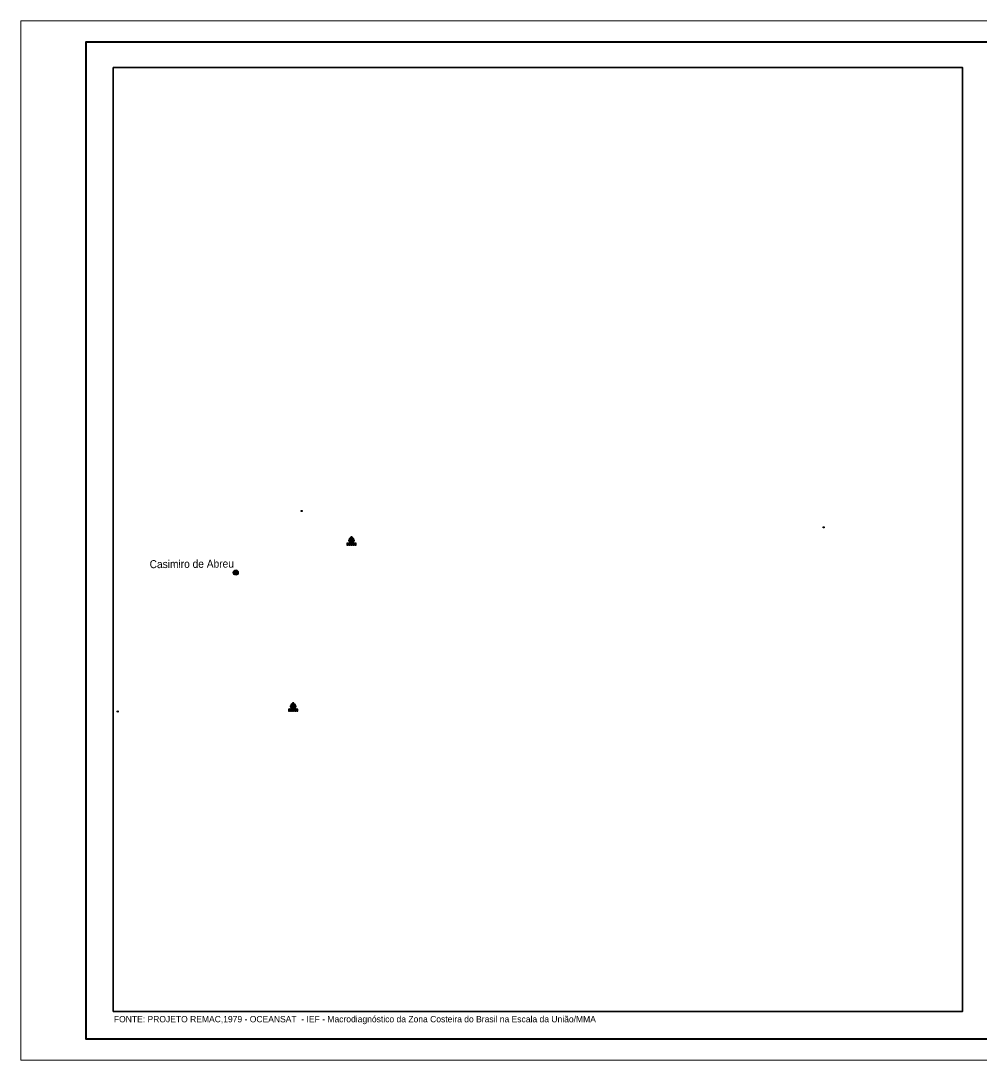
# Model space of a CAD drawing. Extents: x -6.3 to 58.7, y 19.8 to 60.6.
# Drawn here: x -6.29 to 31.28, y 19.82 to 60.58 of the extents above; entities that cross this region are included whole.
import ezdxf
from ezdxf.enums import TextEntityAlignment as Align

# ---------------------------------------------------------------- set-up
doc = ezdxf.new("R2010")
doc.units = 0
doc.header["$LTSCALE"] = 0.092
doc.header["$PDMODE"] = 32
doc.header["$PDSIZE"] = 0.046
for name, color, linetype, lineweight in [('2', 7, 'Continuous', 35), ('4', 7, 'Continuous', 25), ('58', 7, 'Continuous', 13), ('60', 7, 'Continuous', 40), ('63', 7, 'Continuous', 13)]:
    doc.layers.add(name, color=color, linetype=linetype, lineweight=lineweight)
for name, color, linetype in [('34', 7, 'Continuous'), ('37', 7, 'Continuous'), ('42', 7, 'Continuous'), ('44', 7, 'Continuous'), ('57', 7, 'Continuous')]:
    doc.layers.add(name, color=color, linetype=linetype)

msp = doc.modelspace()

# ---------------------------------------------------------------- hatches: boundary and pattern name
at = {"layer": '4'}
msp.add_hatch(color=256, dxfattribs=at).paths.add_polyline_path([(2.2372, 38.94214, 1), (2.03773, 38.94214, 1)])
at = {"layer": '58'}
for points in [[(6.85434, 40.05991), (6.85434, 40.09183), (6.84793, 40.08915), (6.84259, 40.0882), (6.82351, 40.09482), (6.80112, 40.1014), (6.78763, 40.09944), (6.76748, 40.0913), (6.76748, 40.15712), (6.78898, 40.19649), (6.7914, 40.20216), (6.79229, 40.20689), (6.79026, 40.21256), (6.78144, 40.21759), (6.76748, 40.22346), (6.76748, 40.27282), (6.73025, 40.27282), (6.73025, 40.30576), (6.6992, 40.30576), (6.6992, 40.33874), (6.64958, 40.33874), (6.64958, 40.30576), (6.61857, 40.30576), (6.61857, 40.27282), (6.58134, 40.27282), (6.58134, 40.22297), (6.56738, 40.21759), (6.55902, 40.21306), (6.55653, 40.20791), (6.55727, 40.20235), (6.5598, 40.19649), (6.58134, 40.15712), (6.58134, 40.0913), (6.56108, 40.09944), (6.5477, 40.1014), (6.52548, 40.09482), (6.50619, 40.0882), (6.50056, 40.08915), (6.49448, 40.09183), (6.49448, 40.05991), (6.50135, 40.05628), (6.50822, 40.05526), (6.52673, 40.06184), (6.54837, 40.06846), (6.56959, 40.06278), (6.58967, 40.05711), (6.60935, 40.06278), (6.62989, 40.06846), (6.65257, 40.06184), (6.67372, 40.05526), (6.69458, 40.06184), (6.71889, 40.06846), (6.74014, 40.06278), (6.75912, 40.05711), (6.77852, 40.06278), (6.80013, 40.06846), (6.82216, 40.06184), (6.84145, 40.05526), (6.84601, 40.05628)], [(6.85434, 40.01346), (6.85434, 40.04569), (6.84793, 40.043), (6.84281, 40.04206), (6.82408, 40.04868), (6.79927, 40.05526), (6.77862, 40.04939), (6.76001, 40.04361), (6.7411, 40.04939), (6.71764, 40.05526), (6.69497, 40.04868), (6.67461, 40.04206), (6.65374, 40.04868), (6.63118, 40.05526), (6.60886, 40.04939), (6.58878, 40.04361), (6.5692, 40.04939), (6.54709, 40.05526), (6.52605, 40.04868), (6.50687, 40.04206), (6.50096, 40.043), (6.49448, 40.04569), (6.49448, 40.01346), (6.50067, 40.01017), (6.50736, 40.00915), (6.52733, 40.01573), (6.54837, 40.02231), (6.56959, 40.01668), (6.58967, 40.011), (6.60935, 40.01668), (6.62989, 40.02231), (6.65257, 40.01573), (6.67372, 40.00915), (6.69543, 40.01573), (6.71889, 40.02231), (6.73936, 40.01668), (6.75912, 40.011), (6.77919, 40.01668), (6.80013, 40.02231), (6.82138, 40.01573), (6.84145, 40.00915), (6.84804, 40.01017)], [(6.74886, 40.23038), (6.67439, 40.25716), (6.59996, 40.23038), (6.59996, 40.25304), (6.63716, 40.25304), (6.63716, 40.28598), (6.71163, 40.28598), (6.71163, 40.25304), (6.74886, 40.25304)], [(4.56503, 33.55104), (4.56503, 33.58297), (4.55862, 33.58028), (4.55328, 33.57933), (4.5342, 33.58595), (4.51181, 33.59253), (4.49832, 33.59057), (4.47817, 33.58244), (4.47817, 33.64825), (4.49967, 33.68762), (4.50209, 33.6933), (4.50298, 33.69802), (4.50095, 33.7037), (4.49212, 33.70873), (4.47817, 33.71459), (4.47817, 33.76395), (4.44093, 33.76395), (4.44093, 33.79689), (4.40989, 33.79689), (4.40989, 33.82988), (4.36027, 33.82988), (4.36027, 33.79689), (4.32926, 33.79689), (4.32926, 33.76395), (4.29203, 33.76395), (4.29203, 33.7141), (4.27807, 33.70873), (4.26971, 33.70419), (4.26721, 33.69904), (4.26796, 33.69348), (4.27049, 33.68762), (4.29203, 33.64825), (4.29203, 33.58244), (4.27177, 33.59057), (4.25838, 33.59253), (4.23617, 33.58595), (4.21688, 33.57933), (4.21125, 33.58028), (4.20517, 33.58297), (4.20517, 33.55104), (4.21204, 33.54741), (4.21891, 33.54639), (4.23742, 33.55297), (4.25906, 33.55959), (4.28028, 33.55392), (4.30036, 33.54824), (4.32004, 33.55392), (4.34058, 33.55959), (4.36326, 33.55297), (4.3844, 33.54639), (4.40526, 33.55297), (4.42958, 33.55959), (4.45083, 33.55392), (4.4698, 33.54824), (4.4892, 33.55392), (4.51081, 33.55959), (4.53285, 33.55297), (4.55214, 33.54639), (4.5567, 33.54741)], [(4.56503, 33.5046), (4.56503, 33.53682), (4.55862, 33.53414), (4.5535, 33.53319), (4.53477, 33.53981), (4.50996, 33.54639), (4.48931, 33.54053), (4.47069, 33.53474), (4.45179, 33.54053), (4.42833, 33.54639), (4.40566, 33.53981), (4.38529, 33.53319), (4.36443, 33.53981), (4.34186, 33.54639), (4.31954, 33.54053), (4.29947, 33.53474), (4.27989, 33.54053), (4.25778, 33.54639), (4.23674, 33.53981), (4.21755, 33.53319), (4.21164, 33.53414), (4.20517, 33.53682), (4.20517, 33.5046), (4.21136, 33.5013), (4.21805, 33.50028), (4.23802, 33.50686), (4.25906, 33.51345), (4.28028, 33.50781), (4.30036, 33.50214), (4.32004, 33.50781), (4.34058, 33.51345), (4.36326, 33.50686), (4.3844, 33.50028), (4.40612, 33.50686), (4.42958, 33.51345), (4.45005, 33.50781), (4.4698, 33.50214), (4.48988, 33.50781), (4.51081, 33.51345), (4.53207, 33.50686), (4.55214, 33.50028), (4.55873, 33.5013)], [(4.45955, 33.72151), (4.38508, 33.74829), (4.31064, 33.72151), (4.31064, 33.74417), (4.34784, 33.74417), (4.34784, 33.77711), (4.42232, 33.77711), (4.42232, 33.74417), (4.45955, 33.74417)]]:
    msp.add_hatch(color=256, dxfattribs=at).paths.add_polyline_path(points)

# ---------------------------------------------------------------- linework, layer by layer
at = {"layer": '2'}
msp.add_lwpolyline([(-2.6635, 58.74412), (30.62637, 58.74412), (30.62637, 21.73), (-2.6635, 21.73)], close=True, dxfattribs=at)
at = {"layer": '34'}
msp.add_point((25.18317, 40.71409), dxfattribs=at)
at = {"layer": '37'}
msp.add_point((4.719, 41.35238), dxfattribs=at)
at = {"layer": '4'}
msp.add_circle((2.13747, 38.94214), 0.09974, dxfattribs=at)
at = {"layer": '42'}
msp.add_point((-2.48978, 33.49348), dxfattribs=at)
at = {"layer": '44'}
msp.add_point((25.18317, 40.71409), dxfattribs=at)
at = {"layer": '58', "lineweight": 25}
for points in [[(6.85434, 40.05991), (6.85434, 40.09183), (6.84793, 40.08915), (6.84259, 40.0882), (6.82351, 40.09482), (6.80112, 40.1014), (6.78763, 40.09944), (6.76748, 40.0913), (6.76748, 40.15712), (6.78898, 40.19649), (6.7914, 40.20216), (6.79229, 40.20689), (6.79026, 40.21256), (6.78144, 40.21759), (6.76748, 40.22346), (6.76748, 40.27282), (6.73025, 40.27282), (6.73025, 40.30576), (6.6992, 40.30576), (6.6992, 40.33874), (6.64958, 40.33874), (6.64958, 40.30576), (6.61857, 40.30576), (6.61857, 40.27282), (6.58134, 40.27282), (6.58134, 40.22297), (6.56738, 40.21759), (6.55902, 40.21306), (6.55653, 40.20791), (6.55727, 40.20235), (6.5598, 40.19649), (6.58134, 40.15712), (6.58134, 40.0913), (6.56108, 40.09944), (6.5477, 40.1014), (6.52548, 40.09482), (6.50619, 40.0882), (6.50056, 40.08915), (6.49448, 40.09183), (6.49448, 40.05991), (6.50135, 40.05628), (6.50822, 40.05526), (6.52673, 40.06184), (6.54837, 40.06846), (6.56959, 40.06278), (6.58967, 40.05711), (6.60935, 40.06278), (6.62989, 40.06846), (6.65257, 40.06184), (6.67372, 40.05526), (6.69458, 40.06184), (6.71889, 40.06846), (6.74014, 40.06278), (6.75912, 40.05711), (6.77852, 40.06278), (6.80013, 40.06846), (6.82216, 40.06184), (6.84145, 40.05526), (6.84601, 40.05628)], [(6.85434, 40.01346), (6.85434, 40.04569), (6.84793, 40.043), (6.84281, 40.04206), (6.82408, 40.04868), (6.79927, 40.05526), (6.77862, 40.04939), (6.76001, 40.04361), (6.7411, 40.04939), (6.71764, 40.05526), (6.69497, 40.04868), (6.67461, 40.04206), (6.65374, 40.04868), (6.63118, 40.05526), (6.60886, 40.04939), (6.58878, 40.04361), (6.5692, 40.04939), (6.54709, 40.05526), (6.52605, 40.04868), (6.50687, 40.04206), (6.50096, 40.043), (6.49448, 40.04569), (6.49448, 40.01346), (6.50067, 40.01017), (6.50736, 40.00915), (6.52733, 40.01573), (6.54837, 40.02231), (6.56959, 40.01668), (6.58967, 40.011), (6.60935, 40.01668), (6.62989, 40.02231), (6.65257, 40.01573), (6.67372, 40.00915), (6.69543, 40.01573), (6.71889, 40.02231), (6.73936, 40.01668), (6.75912, 40.011), (6.77919, 40.01668), (6.80013, 40.02231), (6.82138, 40.01573), (6.84145, 40.00915), (6.84804, 40.01017)], [(6.74886, 40.23038), (6.67439, 40.25716), (6.59996, 40.23038), (6.59996, 40.25304), (6.63716, 40.25304), (6.63716, 40.28598), (6.71163, 40.28598), (6.71163, 40.25304), (6.74886, 40.25304)], [(4.56503, 33.55104), (4.56503, 33.58297), (4.55862, 33.58028), (4.55328, 33.57933), (4.5342, 33.58595), (4.51181, 33.59253), (4.49832, 33.59057), (4.47817, 33.58244), (4.47817, 33.64825), (4.49967, 33.68762), (4.50209, 33.6933), (4.50298, 33.69802), (4.50095, 33.7037), (4.49212, 33.70873), (4.47817, 33.71459), (4.47817, 33.76395), (4.44093, 33.76395), (4.44093, 33.79689), (4.40989, 33.79689), (4.40989, 33.82988), (4.36027, 33.82988), (4.36027, 33.79689), (4.32926, 33.79689), (4.32926, 33.76395), (4.29203, 33.76395), (4.29203, 33.7141), (4.27807, 33.70873), (4.26971, 33.70419), (4.26721, 33.69904), (4.26796, 33.69348), (4.27049, 33.68762), (4.29203, 33.64825), (4.29203, 33.58244), (4.27177, 33.59057), (4.25838, 33.59253), (4.23617, 33.58595), (4.21688, 33.57933), (4.21125, 33.58028), (4.20517, 33.58297), (4.20517, 33.55104), (4.21204, 33.54741), (4.21891, 33.54639), (4.23742, 33.55297), (4.25906, 33.55959), (4.28028, 33.55392), (4.30036, 33.54824), (4.32004, 33.55392), (4.34058, 33.55959), (4.36326, 33.55297), (4.3844, 33.54639), (4.40526, 33.55297), (4.42958, 33.55959), (4.45083, 33.55392), (4.4698, 33.54824), (4.4892, 33.55392), (4.51081, 33.55959), (4.53285, 33.55297), (4.55214, 33.54639), (4.5567, 33.54741)], [(4.56503, 33.5046), (4.56503, 33.53682), (4.55862, 33.53414), (4.5535, 33.53319), (4.53477, 33.53981), (4.50996, 33.54639), (4.48931, 33.54053), (4.47069, 33.53474), (4.45179, 33.54053), (4.42833, 33.54639), (4.40566, 33.53981), (4.38529, 33.53319), (4.36443, 33.53981), (4.34186, 33.54639), (4.31954, 33.54053), (4.29947, 33.53474), (4.27989, 33.54053), (4.25778, 33.54639), (4.23674, 33.53981), (4.21755, 33.53319), (4.21164, 33.53414), (4.20517, 33.53682), (4.20517, 33.5046), (4.21136, 33.5013), (4.21805, 33.50028), (4.23802, 33.50686), (4.25906, 33.51345), (4.28028, 33.50781), (4.30036, 33.50214), (4.32004, 33.50781), (4.34058, 33.51345), (4.36326, 33.50686), (4.3844, 33.50028), (4.40612, 33.50686), (4.42958, 33.51345), (4.45005, 33.50781), (4.4698, 33.50214), (4.48988, 33.50781), (4.51081, 33.51345), (4.53207, 33.50686), (4.55214, 33.50028), (4.55873, 33.5013)], [(4.45955, 33.72151), (4.38508, 33.74829), (4.31064, 33.72151), (4.31064, 33.74417), (4.34784, 33.74417), (4.34784, 33.77711), (4.42232, 33.77711), (4.42232, 33.74417), (4.45955, 33.74417)]]:
    msp.add_lwpolyline(points, close=True, dxfattribs=at)
at = {"layer": '60'}
for points in [[(-3.73781, 29.96257), (-3.73781, 20.65308), (57.84015, 20.65308), (57.84016, 59.74412), (-3.73781, 59.74412), (-3.73781, 40.1986), (-3.73781, 40.1986)], [(-3.73781, 40.1986), (-3.73781, 29.96257), (-3.73781, 29.96257)]]:
    msp.add_lwpolyline(points, dxfattribs=at)
at = {"layer": '63'}
msp.add_lwpolyline([(-6.28685, 19.8174), (58.67584, 19.8174), (58.67584, 60.5798), (-6.28685, 60.5798)], close=True, dxfattribs=at)

# ---------------------------------------------------------------- texts
at = {"layer": '57', "width": 0.95}
msp.add_text('Casimiro de Abreu', height=0.314, rotation=0.412, dxfattribs=at).set_placement((2.06719, 39.13666), align=Align.RIGHT)
at = {"layer": '58'}
msp.add_text('FONTE: PROJETO REMAC,1979 - OCEANSAT  - IEF - Macrodiagnóstico da Zona Costeira do Brasil na Escala da União/MMA', height=0.2497, dxfattribs=at).set_placement((-2.63811, 21.30398))

doc.saveas('drawing.dxf')
